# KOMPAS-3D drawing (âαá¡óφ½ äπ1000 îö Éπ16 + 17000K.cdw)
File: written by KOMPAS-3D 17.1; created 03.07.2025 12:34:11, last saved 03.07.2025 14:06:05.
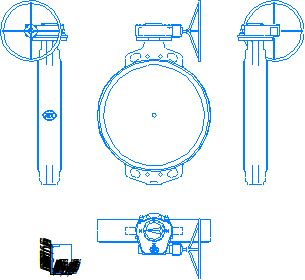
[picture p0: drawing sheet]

Sheet 1: A4, portrait

Title block, sheet 1: sheets: 1; sheet format: A4; stored path: \\adlc.lan\data\АДЛ_ПКД\3D-модели\ADL production\Дисковые поворотные затворы ГРАНВЭЛ\межфланцевый с китайским редуктором Ру16\KOMPAS 2D\Гранвэл Ду1000 МФ Ру16 + 17000K.cdw

Views: Вид 1, Спереди, Проекционный вид 3, Проекционный вид 4
Referenced files in \\adlc.lan\data\АДЛ_ПКД\3D-модели\ADL production\Дисковые поворотные затворы ГРАНВЭЛ\межфланцевый с китайским редуктором Ру16\KOMPAS 3D\: Гранвэл Ду1000 МФ Ру16 + 17000K.m3d
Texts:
  Andrey
  АДЛ
Dimensions and other numbers on the sheet: 1:1; 1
